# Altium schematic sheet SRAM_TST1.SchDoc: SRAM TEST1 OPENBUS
size A4; Engineer: showell; DocumentNumber: 1; Revision: 1.00; SheetNumber: 1; SheetTotal: 1
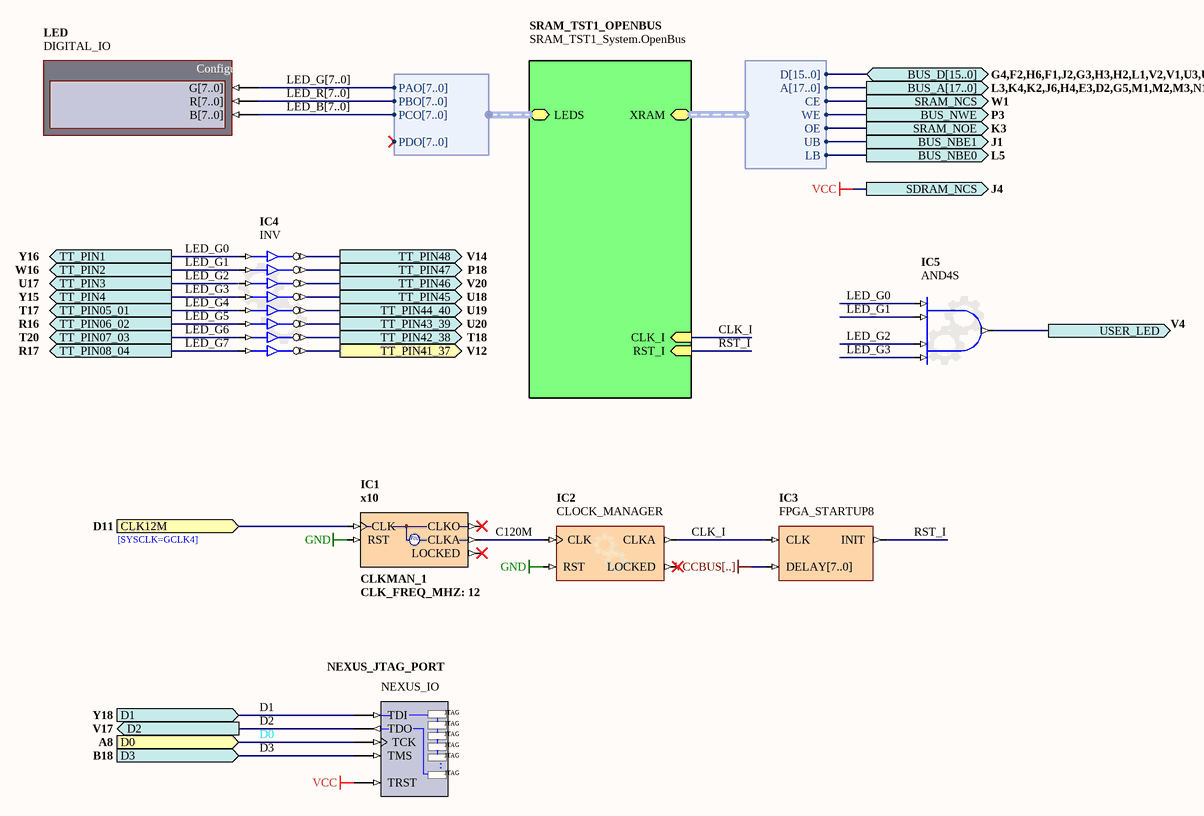
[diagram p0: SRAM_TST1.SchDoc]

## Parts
IC1  CLKMAN_1  CLK_FREQ_MHZ: 12  ClkA_Operation: x10
IC2  CLOCK_MANAGER
IC3  FPGA_STARTUP8
IC4  INV
IC5  AND4S
LED  DIGITAL_IO
NEXUS_JTAG_PORT  NEXUS_IO

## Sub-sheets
SRAM_TST1_OPENBUS = SRAM_TST1_System.OpenBus: RST_I (in), CLK_I (in), LEDS (harness WB_PRTIO_O_4_8), XRAM (harness WB_MEM_CTRL_SRAM16_A18)

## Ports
BUS_A[17..0] (out, see L3,K4,K2,J6,H4,E3,D2,G5,M1,M2,M3,N1,N2,U4,W3,V6,U7,W6), BUS_D[15..0] (bidir, see G4,F2,H6,F1,J2,G3,H3,H2,L1,V2,V1,U3,U1,T3,T2,T1), BUS_NBE0 (out, see L5), BUS_NBE1 (out, see J1), BUS_NWE (out, see P3), CLK12M (in, see D11), D0 (in, see A8), D1 (in, see Y18), D2 (out, see V17), D3 (in, see B18), SDRAM_NCS (out, see J4), SRAM_NCS (out, see W1), SRAM_NOE (out, see K3), TT_PIN1 (out, see Y16), TT_PIN2 (out, see W16), TT_PIN3 (out, see U17), TT_PIN4 (out, see Y15), TT_PIN05_01 (out, see T17), TT_PIN06_02 (out, see R16), TT_PIN07_03 (out, see T20), TT_PIN08_04 (out, see R17), TT_PIN41_37 (out, see V12), TT_PIN42_38 (out, see T18), TT_PIN43_39 (out, see U20), TT_PIN44_40 (out, see U19), TT_PIN45 (out, see U18), TT_PIN46 (out, see V20), TT_PIN47 (out, see P18), TT_PIN48 (out, see V14), USER_LED (out, see V4)

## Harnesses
WB_PRTIO_O_4_8: PAO[7..0], PBO[7..0], PCO[7..0], PDO[7..0]
WB_MEM_CTRL_SRAM16_A18: D[15..0], A[17..0], CE, WE, OE, UB, LB

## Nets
GND: IC1.RST IC2.RST
VCC: NEXUS_JTAG_PORT.TRST ; port SDRAM_NCS
BUS_NBE0: port BUS_NBE0, sheet SRAM_TST1_OPENBUS/XRAM.LB
BUS_NBE1: port BUS_NBE1, sheet SRAM_TST1_OPENBUS/XRAM.UB
BUS_NWE: port BUS_NWE, sheet SRAM_TST1_OPENBUS/XRAM.WE
C120M: IC1.CLKA IC2.CLK
CLK12M: IC1.CLK ; port CLK12M
CLK_I: IC2.CLKA IC3.CLK ; sheet SRAM_TST1_OPENBUS/CLK_I
D0: NEXUS_JTAG_PORT.TCK ; port D0
D1: NEXUS_JTAG_PORT.TDI ; port D1
D2: NEXUS_JTAG_PORT.TDO ; port D2
D3: NEXUS_JTAG_PORT.TMS ; port D3
LED_G0: IC4.I0 IC5.I3 ; port TT_PIN1
LED_G1: IC4.I1 IC5.I2 ; port TT_PIN2
LED_G2: IC4.I2 IC5.I1 ; port TT_PIN3
LED_G3: IC4.I3 IC5.I0 ; port TT_PIN4
LED_G4: IC4.I4 ; port TT_PIN05_01
LED_G5: IC4.I5 ; port TT_PIN06_02
LED_G6: IC4.I6 ; port TT_PIN07_03
LED_G7: IC4.I7 ; port TT_PIN08_04
RST_I: IC3.INIT ; sheet SRAM_TST1_OPENBUS/RST_I
SRAM_NCS: port SRAM_NCS, sheet SRAM_TST1_OPENBUS/XRAM.CE
SRAM_NOE: port SRAM_NOE, sheet SRAM_TST1_OPENBUS/XRAM.OE
TT_PIN41_37: IC4.O7 ; port TT_PIN41_37
TT_PIN42_38: IC4.O6 ; port TT_PIN42_38
TT_PIN43_39: IC4.O5 ; port TT_PIN43_39
TT_PIN44_40: IC4.O4 ; port TT_PIN44_40
TT_PIN45: IC4.O3 ; port TT_PIN45
TT_PIN46: IC4.O2 ; port TT_PIN46
TT_PIN47: IC4.O1 ; port TT_PIN47
TT_PIN48: IC4.O0 ; port TT_PIN48
USER_LED: IC5.O ; port USER_LED

Not connected (* = marked no-connect by the designer): IC1 CLKO* LOCKED*; IC2 LOCKED*; IC3 DELAY[7..0]; LED B[7..0] G[7..0] R[7..0]

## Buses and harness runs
bus LED_B[7..0]
bus LED_G[7..0]
bus LED_R[7..0]

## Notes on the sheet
- [SYSCLK=GCLK4]
- Labels drawn without touching a wire or pin: VCCBUS[..]

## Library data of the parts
IC1 = CLKMAN_1: Single Operational Output Clock Manager; Clk_Count: 1
IC2 = CLOCKMANAGER: Configurable Clock Manager; ConfiguratorName: GENERIC_CLOCKMANAGER; ConfigurationParameters: {}Version[1.0]{}Option_Configuration[object _1: TClockManagerPersist / VersionMajor [ 0 / VersionMinor [ 0 / InputFreq [ 120.000000000000000000 / InputName [ 'CLK' / OutputTargets [ < / item / Name [ 'CLKA' / OutFreqMin [ 50.000000000000000000 / OutFreqMax [ 50.000000000000000000 / OutPostDivider [ 1.000000000000000000 / end> / OutputDevices [ < / item / Name [ 'Spartan3AN' / Valid [ True / OutputActuals [ < / item / Name [ 'CLK0' / Multipler [ 1.000000000000000000 / Divider [ 1.000000000000000000 / OutFreq [ 120.000000000000000000 / OutputMap [ 1 / end / item / Name [ 'CLK90' / Multipler [ 1.000000000000000000 / Divider [ 1.000000000000000000 / OutPhase [ 90.000000000000000000 / OutFreq [ 120.000000000000000000 / OutputMap [ 2 / end / item / Name [ 'CLK180' / Multipler [ 1.000000000000000000 / Divider [ 1.000000000000000000 / OutPhase [ 180.000000000000000000 / OutFreq [ 120.000000000000000000 / OutputMap [ 3 / end / item / Name [ 'CLK270' / Multipler [ 1.000000000000000000 / Divider [ 1.000000000000000000 / OutPhase [ 270.000000000000000000 / OutFreq [ 120.000000000000000000 / OutputMap [ 4 / end / item / Name [ 'CLK2X' / Multipler [ 2.000000000000000000 / Divider [ 1.000000000000000000 / OutFreq [ 240.000000000000000000 / OutputMap [ 5 / end / item / Name [ 'CLKDV' / Multipler [ 1.000000000000000000 / Divider [ 16.000000000000000000 / OutFreq [ 7.500000000000000000 / OutputMap [ 6 / end / item / Name [ 'CLK2X180' / Multipler [ 1.000000000000000000 / Divider [ 1.000000000000000000 / OutPhase [ 180.000000000000000000 / OutFreq [ 240.000000000000000000 / OutputMap [ 7 / end / item / Name [ 'CLKFX' / Multipler [ 5.000000000000000000 / Divider [ 12.000000000000000000 / OutFreq [ 50.000000000000000000 / OutputMap [ 0 / end / item / Name [ 'CLKFX180' / Multipler [ 1.000000000000000000 / Divider [ 1.000000000000000000 / OutPhase [ 180.000000000000000000 / OutFreq [ 50.000000000000000000 / OutputMap [ 8 / end> / InternalActuals [ <> / CustomVars [ <> / end> / MinInputFreq [ 1.000000000000000000 / MaxInputFreq [ 280.000000000000000000 / MinOutputFreq [ 18.000000000000000000 / MaxOutputFreq [ 210.000000000000000000 / MaxOutputCount [ 9 / end]{}
IC3 = FPGA_STARTUP8: FPGA Startup With 8 Bit Delay
IC4 = INV: Configurable Inverter; ConfiguratorName: GENERIC_BUFFER; ConfigurationParameters: {}Version[1.1]{}SignalCount[8]{}SignalWidth0[1]{}OutputOption0[Inverted]{}SignalWidth1[1]{}OutputOption1[Inverted]{}SignalWidth2[1]{}OutputOption2[Inverted]{}SignalWidth3[1]{}OutputOption3[Inverted]{}SignalWidth4[1]{}OutputOption4[Inverted]{}SignalWidth5[1]{}OutputOption5[Inverted]{}SignalWidth6[1]{}OutputOption6[Inverted]{}SignalWidth7[1]{}OutputOption7[Inverted]{}EnableMode[None]{}ShowPinNames[False]{}
IC5 = GATE: Configurable Generic Gate; ConfiguratorName: GENERIC_GATE; ConfigurationParameters: {}Version[1.1]{}GateKind[AND]{}BusInput[False]{}GateInputType[Bit]{}GateOutputOption[Normal]{}BusWidth[8]{}RegisterOutputs[False]{}NegativeClockEdge[False]{}InputCount[4]{}InputInvert0[False]{}InputInvert1[False]{}InputInvert2[False]{}InputInvert3[False]{}
LED = DIGITAL_IO: Configurable Digital IO; NEXUS_CORE: Instrument; NEXUS_JTAG_DEVICE: True; NEXUS_JTAG_ORDER: 0; ConfigurationParameters: {}Version[2.0]{}StorageType[3]{}InterfaceType[Parallel]{}SchCompWidth[140]{}Input0Name[G{1}7..0{2}]{}Input0Width[8]{}Input0InitValue[0]{}Input0Kind[LEDs]{}Input0LEDStyle[Green]{}Input1Name[R{1}7..0{2}]{}Input1Width[8]{}Input1InitValue[0]{}Input1Kind[LEDs]{}Input1LEDStyle[Red]{}Input2Name[B{1}7..0{2}]{}Input2Width[8]{}Input2InitValue[0]{}Input2Kind[LEDs]{}Input2LEDStyle[Blue]{}NoOutputs[ ]{}Designator[LED]{}InternalID[0]{}
NEXUS_JTAG_PORT = NEXUS_JTAG_PORT: Soft Nexus-Chain Connector; NEXUS_JTAG_CONNECTOR: True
